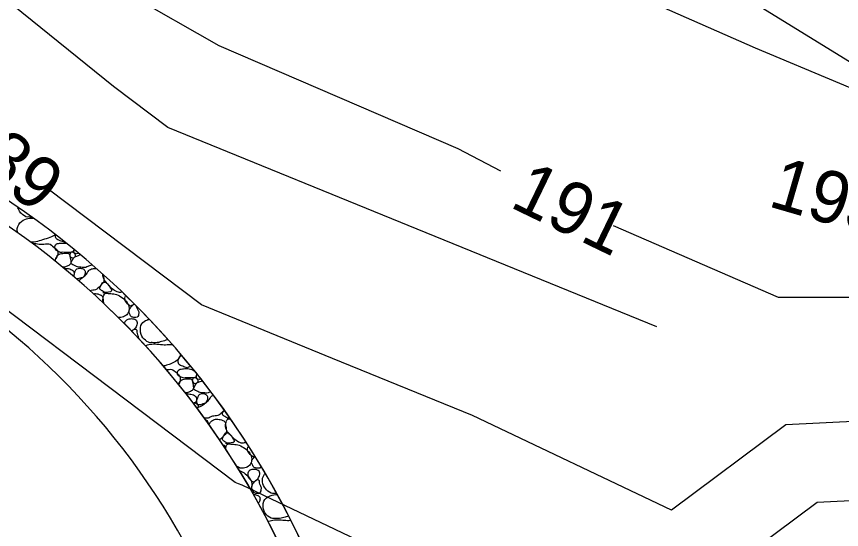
# Model space of a CAD drawing. Extents: x 1385284 to 1385995, y 1975154 to 1975620.
# Drawn here: x 1385491.41 to 1385530.9, y 1975544.39 to 1975568.95 of the extents above; entities that cross this region are included whole.
import ezdxf

# ---------------------------------------------------------------- set-up
doc = ezdxf.new("R2010")
doc.units = 0
for name, color, linetype in [('Default', 7, 'Continuous'), ('DTM CONTOURS_MAJOR', 7, 'Continuous'), ('DTM_CONTOURS_MINOR', 7, 'Continuous'), ('R_Proposed Const Limits', 7, 'Continuous'), ('S_UNDERGROUND_CABLE', 7, 'Continuous')]:
    doc.layers.add(name, color=color, linetype=linetype)

msp = doc.modelspace()

# ---------------------------------------------------------------- linework, layer by layer
at = {"layer": 'Default'}
for radius, end in [(40, 101.9984), (39, 101.9984), (40, 46.1158), (39, 45.8751)]:
    msp.add_arc((1385468.803, 1975526.863), radius, 324.5634, end, dxfattribs=at)
for points in [[(1385491.979, 1975559.352), (1385491.911, 1975559.318), (1385491.688, 1975559.455), (1385491.547, 1975559.628), (1385491.476, 1975559.784), (1385491.462, 1975559.825)], [(1385491.474, 1975558.589), (1385491.422, 1975558.716), (1385491.469, 1975559.034), (1385491.821, 1975559.271), (1385492.091, 1975559.301), (1385492.201, 1975559.296), (1385492.203, 1975559.296)], [(1385492.133, 1975559.347), (1385492.082, 1975559.347), (1385492.03, 1975559.35), (1385491.979, 1975559.352)], [(1385493.255, 1975558.511), (1385493.21, 1975558.46), (1385493.017, 1975558.358), (1385492.656, 1975558.26), (1385492.322, 1975558.143), (1385492.127, 1975558.143), (1385492.092, 1975558.144)], [(1385493.712, 1975558.145), (1385493.64, 1975558.155), (1385493.495, 1975558.224), (1385493.279, 1975558.293), (1385493.269, 1975558.438), (1385493.278, 1975558.493)], [(1385492.161, 1975558.094), (1385492.173, 1975558.094), (1385492.354, 1975558.087), (1385492.617, 1975558.024), (1385492.983, 1975558.117), (1385493.187, 1975557.912), (1385493.439, 1975557.708), (1385493.344, 1975557.403), (1385493.238, 1975557.288), (1385493.219, 1975557.271)], [(1385493.607, 1975557.662), (1385493.551, 1975557.638), (1385493.406, 1975557.696), (1385493.245, 1975557.782), (1385493.234, 1975557.949), (1385493.311, 1975558.08), (1385493.509, 1975558.096), (1385493.669, 1975558.105), (1385493.79, 1975558.094)], [(1385493.719, 1975558.149), (1385493.717, 1975558.148), (1385493.714, 1975558.146), (1385493.712, 1975558.145)], [(1385493.275, 1975557.227), (1385493.273, 1975557.253), (1385493.287, 1975557.354), (1385493.385, 1975557.566), (1385493.601, 1975557.615), (1385493.962, 1975557.645), (1385493.965, 1975557.403), (1385494.047, 1975557.092), (1385493.863, 1975557.014), (1385493.76, 1975556.966), (1385493.712, 1975556.942)], [(1385494.167, 1975557.789), (1385494.167, 1975557.785), (1385494.158, 1975557.742), (1385494.092, 1975557.654), (1385493.887, 1975557.661), (1385493.727, 1975557.656), (1385493.607, 1975557.662)], [(1385494.15, 1975557.396), (1385494.113, 1975557.396), (1385494.028, 1975557.394), (1385493.949, 1975557.476), (1385493.957, 1975557.594), (1385494.041, 1975557.696), (1385494.168, 1975557.645), (1385494.272, 1975557.485), (1385494.184, 1975557.425), (1385494.15, 1975557.396)], [(1385494.379, 1975557.611), (1385494.349, 1975557.604), (1385494.281, 1975557.575), (1385494.173, 1975557.612), (1385494.145, 1975557.701), (1385494.157, 1975557.759), (1385494.166, 1975557.79)], [(1385494.435, 1975556.942), (1385494.364, 1975556.937), (1385494.228, 1975557.017), (1385493.969, 1975557.106), (1385494.083, 1975557.275), (1385494.162, 1975557.462), (1385494.341, 1975557.473), (1385494.431, 1975557.541), (1385494.447, 1975557.553)], [(1385493.712, 1975556.942), (1385493.666, 1975556.949), (1385493.62, 1975556.963), (1385493.575, 1975556.981)], [(1385493.674, 1975556.897), (1385493.735, 1975556.896), (1385493.9, 1975556.892), (1385494.129, 1975556.803), (1385494.183, 1975556.623), (1385494.152, 1975556.527), (1385494.139, 1975556.505)], [(1385494.147, 1975556.498), (1385494.154, 1975556.545), (1385494.177, 1975556.631), (1385494.22, 1975556.756), (1385494.281, 1975556.881), (1385494.431, 1975556.897), (1385494.603, 1975556.893), (1385494.716, 1975556.766), (1385494.692, 1975556.606), (1385494.631, 1975556.489), (1385494.578, 1975556.459)], [(1385494.381, 1975556.301), (1385494.387, 1975556.305), (1385494.454, 1975556.355), (1385494.587, 1975556.462), (1385494.766, 1975556.604), (1385494.861, 1975556.81), (1385495.039, 1975556.886), (1385495.168, 1975556.894), (1385495.228, 1975556.891)], [(1385495.051, 1975557.044), (1385494.988, 1975557.036), (1385494.862, 1975557.027), (1385494.68, 1975556.883), (1385494.514, 1975556.962), (1385494.435, 1975556.942)], [(1385494.578, 1975556.459), (1385494.531, 1975556.444), (1385494.435, 1975556.421), (1385494.335, 1975556.395), (1385494.283, 1975556.387), (1385494.28, 1975556.386)], [(1385495.548, 1975556.599), (1385495.549, 1975556.589), (1385495.567, 1975556.484), (1385495.629, 1975556.252), (1385495.415, 1975556.045), (1385495.208, 1975555.835), (1385495.018, 1975555.843), (1385494.916, 1975555.823)], [(1385496.344, 1975555.739), (1385496.273, 1975555.736), (1385496.09, 1975555.82), (1385495.893, 1975556.002), (1385495.683, 1975556.226), (1385495.558, 1975556.438), (1385495.542, 1975556.571), (1385495.542, 1975556.604)], [(1385495.662, 1975555.739), (1385495.614, 1975555.738), (1385495.518, 1975555.811), (1385495.355, 1975555.904), (1385495.465, 1975556.089), (1385495.512, 1975556.254), (1385495.693, 1975556.228), (1385495.813, 1975556.123), (1385495.88, 1975555.979), (1385496.067, 1975555.73), (1385495.318, 1975555.747), (1385495.704, 1975555.737), (1385495.695, 1975555.739)], [(1385495.074, 1975555.678), (1385495.16, 1975555.695), (1385495.296, 1975555.674), (1385495.551, 1975555.588), (1385495.54, 1975555.404), (1385495.574, 1975555.266), (1385495.581, 1975555.216)], [(1385495.599, 1975555.2), (1385495.583, 1975555.234), (1385495.531, 1975555.329), (1385495.557, 1975555.489), (1385495.628, 1975555.731), (1385495.857, 1975555.679), (1385496.127, 1975555.684), (1385496.416, 1975555.539), (1385496.673, 1975555.328), (1385496.821, 1975555.069), (1385496.783, 1975554.752), (1385496.597, 1975554.58), (1385496.429, 1975554.535), (1385496.344, 1975554.536)], [(1385496.463, 1975555.754), (1385496.424, 1975555.743), (1385496.384, 1975555.739), (1385496.344, 1975555.739)], [(1385496.922, 1975555.11), (1385496.89, 1975555.036), (1385496.686, 1975555.217), (1385496.584, 1975555.396), (1385496.598, 1975555.536), (1385496.635, 1975555.582), (1385496.637, 1975555.583)], [(1385497.248, 1975554.641), (1385497.238, 1975554.616), (1385497.19, 1975554.526), (1385497.067, 1975554.541), (1385496.889, 1975554.56), (1385496.851, 1975554.676), (1385496.777, 1975554.785), (1385496.815, 1975554.949), (1385496.91, 1975555.061), (1385496.98, 1975555.142), (1385497.029, 1975555.172), (1385497.047, 1975555.179)], [(1385497.04, 1975555.186), (1385497.025, 1975555.172), (1385496.987, 1975555.138), (1385496.947, 1975555.12), (1385496.922, 1975555.11)], [(1385497.138, 1975555.089), (1385497.138, 1975555.085), (1385497.158, 1975555.02), (1385497.211, 1975554.911), (1385497.293, 1975554.775), (1385497.229, 1975554.671), (1385497.248, 1975554.641)], [(1385496.344, 1975554.536), (1385496.318, 1975554.535), (1385496.292, 1975554.538), (1385496.266, 1975554.545)], [(1385496.603, 1975554.213), (1385496.602, 1975554.22), (1385496.591, 1975554.271), (1385496.634, 1975554.413), (1385496.798, 1975554.486), (1385497.026, 1975554.493), (1385497.215, 1975554.368), (1385497.164, 1975554.13), (1385497.051, 1975553.965), (1385496.947, 1975553.917), (1385496.922, 1975553.907)], [(1385497.849, 1975553.337), (1385497.781, 1975553.303), (1385497.558, 1975553.44), (1385497.342, 1975553.685), (1385497.313, 1975554.203), (1385497.587, 1975554.413), (1385497.752, 1975554.453), (1385497.756, 1975554.454)], [(1385496.922, 1975553.907), (1385496.919, 1975553.901), (1385496.916, 1975553.896), (1385496.912, 1975553.892)], [(1385496.925, 1975553.877), (1385496.947, 1975553.901), (1385496.989, 1975553.947), (1385497.067, 1975554.002), (1385497.192, 1975553.951), (1385497.149, 1975553.834), (1385497.211, 1975553.708), (1385497.244, 1975553.593), (1385497.249, 1975553.538), (1385497.249, 1975553.533)], [(1385497.58, 1975553.181), (1385497.631, 1975553.211), (1385497.793, 1975553.268), (1385498.127, 1975553.285), (1385498.486, 1975553.212), (1385498.761, 1975553.267), (1385498.855, 1975553.241), (1385498.869, 1975553.236)], [(1385498.661, 1975553.475), (1385498.619, 1975553.462), (1385498.421, 1975553.411), (1385498.154, 1975553.319), (1385497.921, 1975553.334), (1385497.849, 1975553.337)], [(1385499.243, 1975552.806), (1385499.252, 1975552.71), (1385499.162, 1975552.518), (1385498.894, 1975552.345), (1385498.651, 1975552.269), (1385498.47, 1975552.217), (1385498.438, 1975552.208)], [(1385499.581, 1975552.13), (1385499.509, 1975552.14), (1385499.365, 1975552.21), (1385499.141, 1975552.28), (1385499.144, 1975552.508), (1385499.204, 1975552.662), (1385499.287, 1975552.729), (1385499.301, 1975552.739)], [(1385498.58, 1975552.044), (1385498.661, 1975552.041), (1385498.854, 1975552.1), (1385499.056, 1975551.897), (1385499.299, 1975551.698), (1385499.235, 1975551.439), (1385499.16, 1975551.336)], [(1385499.476, 1975551.647), (1385499.421, 1975551.623), (1385499.276, 1975551.681), (1385499.114, 1975551.767), (1385499.104, 1975551.934), (1385499.18, 1975552.066), (1385499.4, 1975552.084), (1385499.669, 1975552.108), (1385499.857, 1975552.036), (1385499.916, 1975551.991)], [(1385499.742, 1975552.208), (1385499.737, 1975552.206), (1385499.683, 1975552.18), (1385499.629, 1975552.155), (1385499.581, 1975552.13)], [(1385500.03, 1975551.85), (1385500.039, 1975551.82), (1385500.041, 1975551.763), (1385499.962, 1975551.639), (1385499.756, 1975551.646), (1385499.596, 1975551.641), (1385499.476, 1975551.647)], [(1385500.02, 1975551.381), (1385499.982, 1975551.381), (1385499.898, 1975551.379), (1385499.818, 1975551.461), (1385499.826, 1975551.579), (1385499.91, 1975551.681), (1385500.038, 1975551.631), (1385500.141, 1975551.47), (1385500.053, 1975551.41), (1385500.02, 1975551.381)], [(1385500.236, 1975551.593), (1385500.21, 1975551.587), (1385500.147, 1975551.561), (1385500.043, 1975551.597), (1385500.015, 1975551.703), (1385500.034, 1975551.778), (1385500.049, 1975551.826)], [(1385499.161, 1975551.335), (1385499.178, 1975551.393), (1385499.27, 1975551.555), (1385499.47, 1975551.6), (1385499.832, 1975551.63), (1385499.835, 1975551.388), (1385499.917, 1975551.077), (1385499.732, 1975551), (1385499.629, 1975550.952), (1385499.581, 1975550.927)], [(1385500.305, 1975550.927), (1385500.233, 1975550.922), (1385500.098, 1975551.002), (1385499.838, 1975551.092), (1385499.952, 1975551.26), (1385500.031, 1975551.447), (1385500.203, 1975551.453), (1385500.285, 1975551.514), (1385500.294, 1975551.521)], [(1385499.581, 1975550.927), (1385499.542, 1975550.933), (1385499.503, 1975550.944), (1385499.464, 1975550.958)], [(1385499.525, 1975550.882), (1385499.592, 1975550.882), (1385499.764, 1975550.88), (1385499.998, 1975550.788), (1385500.057, 1975550.602), (1385499.97, 1975550.44), (1385499.892, 1975550.444), (1385499.861, 1975550.444)], [(1385500.447, 1975550.444), (1385500.4, 1975550.429), (1385500.304, 1975550.406), (1385500.169, 1975550.352), (1385500.043, 1975550.394), (1385500.015, 1975550.501), (1385500.046, 1975550.614), (1385500.089, 1975550.742), (1385500.15, 1975550.866), (1385500.3, 1975550.882), (1385500.472, 1975550.878), (1385500.585, 1975550.751), (1385500.561, 1975550.591), (1385500.5, 1975550.474), (1385500.447, 1975550.444)], [(1385500.703, 1975550.987), (1385500.654, 1975550.968), (1385500.536, 1975550.874), (1385500.384, 1975550.947), (1385500.305, 1975550.927)], [(1385499.876, 1975550.423), (1385499.886, 1975550.432), (1385499.935, 1975550.469), (1385500.038, 1975550.428), (1385500.146, 1975550.274), (1385500.071, 1975550.22), (1385500.044, 1975550.198)], [(1385500.044, 1975550.197), (1385500.112, 1975550.244), (1385500.264, 1975550.295), (1385500.456, 1975550.447), (1385500.635, 1975550.589), (1385500.711, 1975550.759), (1385500.791, 1975550.811), (1385500.822, 1975550.826)], [(1385501.358, 1975550.106), (1385501.331, 1975550.074), (1385501.243, 1975549.984), (1385501.062, 1975549.808), (1385500.786, 1975549.84), (1385500.573, 1975549.693), (1385500.448, 1975549.721), (1385500.393, 1975549.727)], [(1385501.531, 1975549.724), (1385501.484, 1975549.723), (1385501.388, 1975549.796), (1385501.225, 1975549.889), (1385501.305, 1975550.023), (1385501.343, 1975550.087), (1385501.356, 1975550.107)], [(1385500.62, 1975549.414), (1385500.623, 1975549.416), (1385500.667, 1975549.461), (1385500.73, 1975549.592), (1385500.942, 1975549.685), (1385501.157, 1975549.659), (1385501.42, 1975549.573), (1385501.412, 1975549.345), (1385501.498, 1975549.034), (1385501.293, 1975548.836), (1385501.181, 1975548.71), (1385501.124, 1975548.678)], [(1385502.213, 1975548.521), (1385502.142, 1975548.518), (1385501.96, 1975548.602), (1385501.763, 1975548.784), (1385501.552, 1975549.008), (1385501.394, 1975549.248), (1385501.426, 1975549.474), (1385501.49, 1975549.706), (1385501.605, 1975549.676), (1385501.656, 1975549.671)], [(1385501.615, 1975549.731), (1385501.573, 1975549.728), (1385501.407, 1975549.726), (1385501.573, 1975549.722), (1385501.565, 1975549.724)], [(1385500.446, 1975549.655), (1385500.459, 1975549.651), (1385500.51, 1975549.631), (1385500.561, 1975549.573), (1385500.575, 1975549.508), (1385500.576, 1975549.479)], [(1385501.531, 1975548.521), (1385501.484, 1975548.52), (1385501.388, 1975548.593), (1385501.225, 1975548.686), (1385501.334, 1975548.871), (1385501.382, 1975549.036), (1385501.563, 1975549.01), (1385501.682, 1975548.905), (1385501.749, 1975548.761), (1385501.936, 1975548.512), (1385501.187, 1975548.529), (1385501.573, 1975548.519), (1385501.565, 1975548.521)], [(1385501.416, 1975548.25), (1385501.418, 1975548.263), (1385501.432, 1975548.335), (1385501.497, 1975548.514), (1385501.726, 1975548.461), (1385501.996, 1975548.467), (1385502.285, 1975548.322), (1385502.542, 1975548.11), (1385502.69, 1975547.851), (1385502.652, 1975547.534), (1385502.466, 1975547.362), (1385502.298, 1975547.318), (1385502.213, 1975547.318)], [(1385502.403, 1975548.559), (1385502.34, 1975548.533), (1385502.276, 1975548.521), (1385502.213, 1975548.521)], [(1385501.285, 1975548.443), (1385501.31, 1975548.435), (1385501.378, 1975548.38), (1385501.399, 1975548.311), (1385501.406, 1975548.266)], [(1385502.791, 1975547.892), (1385502.76, 1975547.818), (1385502.555, 1975547.999), (1385502.453, 1975548.178), (1385502.47, 1975548.325), (1385502.512, 1975548.372), (1385502.517, 1975548.377)], [(1385503.116, 1975547.419), (1385503.107, 1975547.396), (1385503.057, 1975547.308), (1385502.936, 1975547.323), (1385502.758, 1975547.342), (1385502.72, 1975547.458), (1385502.646, 1975547.567), (1385502.685, 1975547.731), (1385502.764, 1975547.826), (1385502.812, 1975547.882), (1385502.822, 1975547.893)], [(1385502.816, 1975547.903), (1385502.808, 1975547.899), (1385502.8, 1975547.896), (1385502.791, 1975547.892)], [(1385502.213, 1975547.318), (1385502.142, 1975547.315), (1385502.037, 1975547.362), (1385501.948, 1975547.423), (1385501.925, 1975547.44)], [(1385502.068, 1975547.215), (1385502.131, 1975547.193), (1385502.302, 1975547.105), (1385502.542, 1975546.907), (1385502.69, 1975546.648), (1385502.675, 1975546.403), (1385502.621, 1975546.321), (1385502.606, 1975546.301)], [(1385502.791, 1975546.689), (1385502.76, 1975546.615), (1385502.555, 1975546.797), (1385502.453, 1975546.975), (1385502.504, 1975547.195), (1385502.668, 1975547.268), (1385502.895, 1975547.275), (1385503.085, 1975547.15), (1385503.033, 1975546.912), (1385502.92, 1975546.747), (1385502.817, 1975546.7), (1385502.791, 1975546.689)], [(1385503.718, 1975546.119), (1385503.65, 1975546.085), (1385503.427, 1975546.222), (1385503.212, 1975546.468), (1385503.143, 1975546.865), (1385503.282, 1975547.031), (1385503.319, 1975547.066)], [(1385503.117, 1975546.22), (1385503.107, 1975546.195), (1385503.059, 1975546.105), (1385502.936, 1975546.12), (1385502.758, 1975546.139), (1385502.72, 1975546.255), (1385502.646, 1975546.364), (1385502.685, 1975546.528), (1385502.779, 1975546.64), (1385502.856, 1975546.728), (1385502.936, 1975546.784), (1385503.061, 1975546.733), (1385503.018, 1975546.616), (1385503.08, 1975546.49), (1385503.162, 1975546.354), (1385503.099, 1975546.25), (1385503.117, 1975546.22)], [(1385503.865, 1975546.114), (1385503.816, 1975546.114), (1385503.767, 1975546.117), (1385503.718, 1975546.119)], [(1385502.743, 1975546.063), (1385502.795, 1975546.068), (1385502.919, 1975546.053), (1385503.085, 1975545.947), (1385503.057, 1975545.76), (1385503.006, 1975545.676), (1385502.982, 1975545.645)], [(1385503.718, 1975544.916), (1385503.65, 1975544.882), (1385503.427, 1975545.019), (1385503.212, 1975545.265), (1385503.182, 1975545.782), (1385503.545, 1975546.032), (1385503.798, 1975546.065), (1385503.891, 1975546.065)], [(1385504.437, 1975545.026), (1385504.426, 1975545.023), (1385504.259, 1975544.979), (1385504.023, 1975544.898), (1385503.79, 1975544.913), (1385503.718, 1975544.916)], [(1385503.448, 1975544.759), (1385503.499, 1975544.789), (1385503.662, 1975544.847), (1385503.996, 1975544.864), (1385504.306, 1975544.818), (1385504.508, 1975544.827), (1385504.542, 1975544.828)]]:
    msp.add_open_spline(points, degree=3, dxfattribs=at)
at = {"layer": 'DTM CONTOURS_MAJOR'}
msp.add_lwpolyline([(1385522.056, 1975554.091), (1385511.021, 1975558.588), (1385498.653, 1975563.634), (1385496.045, 1975565.603), (1385483.372, 1975575.846), (1385482.113, 1975576.798), (1385470.917, 1975585.913), (1385468.561, 1975587.657), (1385452.473, 1975594.716), (1385451.663, 1975595.064), (1385435.988, 1975601.935), (1385435.363, 1975602.12)], dxfattribs=at)
at = {"layer": 'DTM_CONTOURS_MINOR'}
for points in [[(1385539.708, 1975568.446), (1385539.397, 1975568.104), (1385539.548, 1975566.963), (1385534.851, 1975564.048), (1385526.785, 1975567.431), (1385514.475, 1975572.866), (1385510.817, 1975574.983), (1385492.798, 1975585.323), (1385478.08, 1975593.952), (1385471.605, 1975597.675), (1385463.769, 1975600.162), (1385448.691, 1975607.406)], [(1385566.44, 1975607.406), (1385566.403, 1975602.698), (1385564.907, 1975594.54), (1385562.955, 1975591.481), (1385558.587, 1975584.007), (1385555.274, 1975578.535), (1385551.48, 1975572.062), (1385547.571, 1975565.618), (1385548.146, 1975562.577), (1385545.187, 1975557.988), (1385540.742, 1975552.033), (1385537.252, 1975549.84), (1385528.237, 1975549.401), (1385522.764, 1975545.306), (1385513.238, 1975549.849), (1385506.531, 1975552.582), (1385500.268, 1975555.138), (1385492.923, 1975560.68)], [(1385514.589, 1975561.539), (1385512.543, 1975562.616), (1385501.115, 1975567.556), (1385496.853, 1975569.996), (1385485.373, 1975578.699), (1385479.845, 1975581.695), (1385469.098, 1975589.652), (1385457.886, 1975594.571), (1385449.838, 1975598.029), (1385440.126, 1975602.287), (1385428.54, 1975605.711), (1385423.05, 1975606.119), (1385417.264, 1975606.549), (1385404.449, 1975607.001), (1385394.252, 1975605.116), (1385386.475, 1975604.033), (1385375.432, 1975601.945), (1385366.349, 1975599.957), (1385356.912, 1975595.013), (1385349.735, 1975591.254), (1385341.987, 1975580.912), (1385341.879, 1975572.907)], [(1385534.545, 1975545.92), (1385529.729, 1975545.685), (1385519.689, 1975538.171), (1385502.211, 1975546.507), (1385502.041, 1975546.577), (1385501.882, 1975546.641), (1385484.577, 1975559.699), (1385484.107, 1975560.079), (1385467.301, 1975572.783), (1385466.481, 1975573.451), (1385456.805, 1975579.862), (1385454.291, 1975581.019), (1385445.143, 1975586.839), (1385441.234, 1975588.622), (1385430.98, 1975591.874), (1385429.467, 1975591.97), (1385421.762, 1975594.796), (1385414.234, 1975590.496), (1385407.886, 1975581.531), (1385406.491, 1975581.15), (1385406.184, 1975579.91)], [(1385536.466, 1975555.492), (1385527.883, 1975555.491), (1385519.988, 1975558.929)]]:
    msp.add_lwpolyline(points, dxfattribs=at)
at = {"layer": 'R_Proposed Const Limits'}
msp.add_arc((1385468.803, 1975526.863), 35, 324.5634, 101.9984, dxfattribs=at)
at = {"layer": 'S_UNDERGROUND_CABLE'}
msp.add_line((1385526.194, 1975569.941), (1385618.813, 1975512.534), dxfattribs=at)

# ---------------------------------------------------------------- texts
at = {"layer": 'Default'}
for s, rotation, p in [('189', 322.0937, (1385487.965, 1975562.899)), ('193', 343.8029, (1385527.32, 1975559.883)), ('191', 334.2036, (1385514.956, 1975559.859))]:
    msp.add_text(s, height=2.5, rotation=rotation, dxfattribs=at).set_placement(p)

doc.saveas('drawing.dxf')
